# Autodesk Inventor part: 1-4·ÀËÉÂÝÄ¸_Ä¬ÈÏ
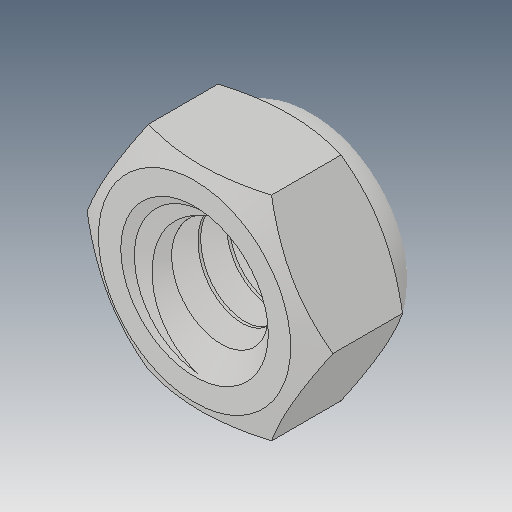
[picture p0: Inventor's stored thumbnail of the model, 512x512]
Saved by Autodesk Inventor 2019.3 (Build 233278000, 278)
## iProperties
Created: 2010-06
Part Number: 1-4·ÀËÉÂÝÄ¸_Ä¬ÈÏ
Material: Ogólny
Document SubType Name: Modeling
Designer: CADENGINEERING4
Density: 1 g/cm^3
Appearance: Domyślna
Author: CADENGINEERING4
Revision Number: ÈÎºÎ
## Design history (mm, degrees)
feature "NONE"
node "Bryła1"
